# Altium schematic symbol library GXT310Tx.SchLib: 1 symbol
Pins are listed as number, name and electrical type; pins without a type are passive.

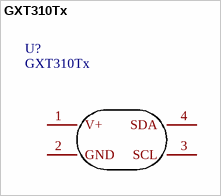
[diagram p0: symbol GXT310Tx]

## GXT310Tx
designator U?
footprint MCLGA-4_L3.0-W3.0-P1.80-BL
pins: 1 V+, 2 GND, 3 SCL, 4 SDA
